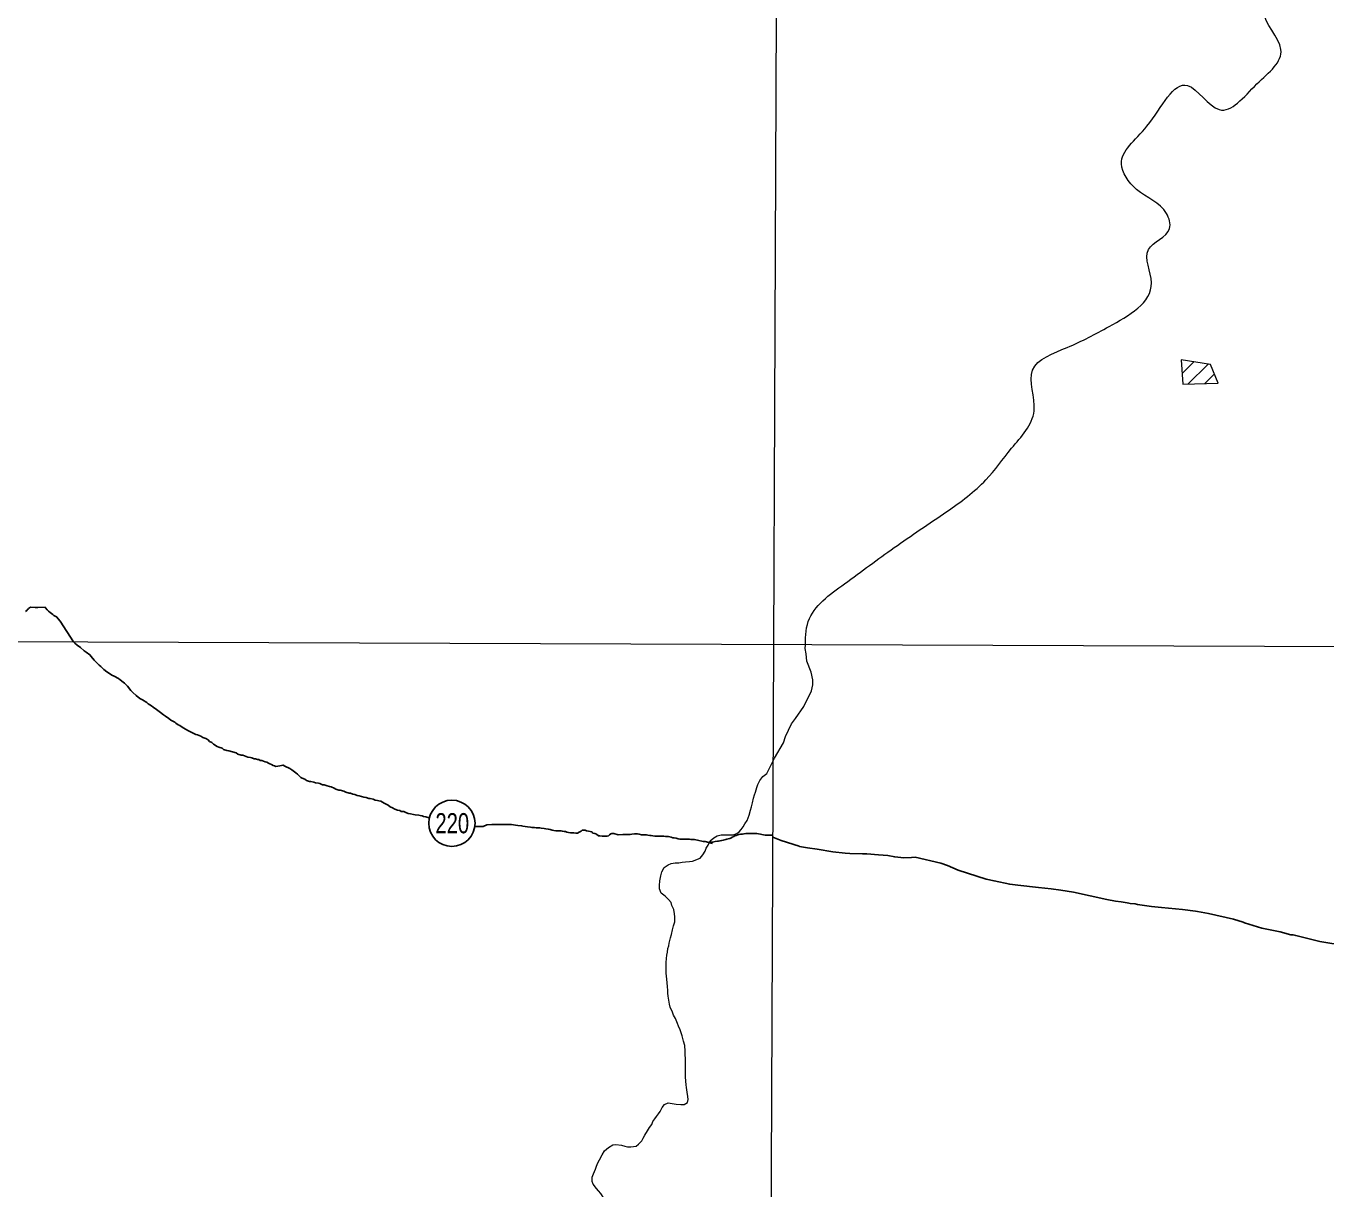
# Model space of a CAD drawing. Extents: x 553962 to 842807, y 8883888 to 9032388.
# Drawn here: x 593998 to 598511, y 8908040 to 8912077 of the extents above; entities that cross this region are included whole.
import ezdxf
from ezdxf.enums import TextEntityAlignment as Align

# ---------------------------------------------------------------- set-up
doc = ezdxf.new("R2010")
doc.units = 0
doc.header["$LTSCALE"] = 160
doc.layers.add('6', color=7, linetype='Continuous', lineweight=13)

msp = doc.modelspace()

# ---------------------------------------------------------------- linework, layer by layer
at = {"layer": '6'}
for p, q in [((598011.9, 8910870), (598052.8, 8910910.9)), ((598032.2, 8910833.7), (598101.8, 8910903.3)), ((598090.8, 8910835.7), (598123.8, 8910868.8)), ((576954.3, 8910001), (623612.7, 8909833))]:
    msp.add_line(p, q, dxfattribs=at)
at = {"layer": '6', "lineweight": 25}
msp.add_line((596590.3, 8909268.1), (596591.5, 8909261.3), dxfattribs=at)
at = {"layer": '6'}
for points in [[(596655.5, 8924715.8), (596593.3, 8909930.3), (596541.3, 8898204.5)], [(596627.8, 8909589.1), (596635.4, 8909611), (596655.3, 8909654), (596669.8, 8909672.5), (596698.4, 8909714.8), (596724.9, 8909769.1), (596729.8, 8909790.3), (596729.5, 8909807.5), (596724.5, 8909833.3), (596708.7, 8909872.6), (596708.4, 8909884.4), (596706.9, 8909897.8), (596703.8, 8909915.9)], [(596275.7, 8909174.6), (596288.2, 8909175.5), (596301.7, 8909176.9), (596311.7, 8909178.4), (596338.8, 8909188.3), (596347.8, 8909199.7), (596355.9, 8909212.7), (596359.4, 8909222.7), (596366.5, 8909233.7), (596373.6, 8909248.1), (596385.6, 8909259.1), (596397.7, 8909265.5), (596411.7, 8909268.9), (596453.7, 8909268.7), (596465.8, 8909273.5), (596474, 8909279.4), (596480.5, 8909287.6), (596487.5, 8909297.6), (596493.4, 8909307), (596502, 8909319.5), (596508.7, 8909337), (596514, 8909354.6), (596516.7, 8909367), (596520.3, 8909380.5), (596523.9, 8909397), (596527.4, 8909408), (596531, 8909417.9), (596535.1, 8909433.9), (596539.1, 8909443.9), (596545.7, 8909457.9), (596556.2, 8909471.9), (596569.8, 8909481.8), (596597.3, 8909535.3), (596627.8, 8909589.1)], [(596220.8, 8908789.1), (596221, 8908826.6), (596222.1, 8908840.6), (596223.1, 8908851.1), (596225.2, 8908861.6), (596226.2, 8908874.6), (596230.3, 8908884.1), (596230.8, 8908893.6), (596235.4, 8908912.1), (596239, 8908923.6), (596243, 8908940.1), (596246.6, 8908953.6), (596250.7, 8908967.6), (596250.8, 8908984.6), (596249.8, 8908995.6), (596247.4, 8909010.6), (596240.9, 8909023.6), (596237.5, 8909034.2), (596228.5, 8909045.2), (596217.1, 8909056.8), (596203.1, 8909066.9), (596197.7, 8909081.4), (596197.7, 8909093.9), (596198.3, 8909109.9), (596201.9, 8909127.4), (596205.9, 8909140.9), (596214, 8909155.9), (596227.1, 8909164.8), (596238.6, 8909169.8), (596251.6, 8909171.7), (596265.1, 8909172.6), (596275.7, 8909174.6)], [(595978.5, 8908119.2), (595983.6, 8908131.2), (595989.1, 8908141.2), (595998.7, 8908158.2), (596006.8, 8908172.2), (596020.8, 8908184.6), (596035.4, 8908193.5), (596045.9, 8908194), (596065.9, 8908192.4), (596076.9, 8908188.3), (596086.9, 8908186.8), (596097.9, 8908186.7), (596116.5, 8908188.6), (596125, 8908195.1), (596136.1, 8908207.5), (596141.1, 8908216), (596146.2, 8908226.5), (596156.2, 8908242.4), (596163.3, 8908252.9), (596170.8, 8908264.4), (596174.9, 8908274.4), (596180.9, 8908283.3), (596187, 8908291.3), (596194, 8908300.8), (596199.6, 8908309.3), (596207.2, 8908323.2), (596215.2, 8908333.7), (596227.7, 8908339.2), (596241.2, 8908336.6), (596255.7, 8908334.5), (596271.8, 8908333.4), (596283.3, 8908333.4), (596295.1, 8908339.9), (596297.3, 8908350.8), (596295.4, 8908360.8), (596293, 8908375.8), (596291.5, 8908391.9), (596290.6, 8908401.9), (596288.6, 8908413.9), (596288.2, 8908429.9), (596287.8, 8908446.9), (596288, 8908490.5), (596286.6, 8908508), (596286.1, 8908518), (596285.2, 8908537.5), (596281.3, 8908553.1), (596275.8, 8908571.1), (596272.4, 8908582.1), (596269.5, 8908592.7), (596263.5, 8908604.7), (596260, 8908614.2), (596252.6, 8908632.3), (596246.7, 8908642.8), (596243.2, 8908653.3), (596234.8, 8908671.4), (596232.8, 8908681.4), (596229.9, 8908695.4), (596228, 8908709), (596227, 8908719.5), (596226, 8908729), (596225.1, 8908743), (596223.7, 8908756), (596222.7, 8908768.5), (596221.8, 8908778.6), (596220.8, 8908789.1)], [(596014.3, 8907828.6), (596014.4, 8907881.9), (596016.5, 8907895.9), (596018.1, 8907906.9), (596021.6, 8907919.9), (596026.2, 8907932.8), (596029.8, 8907948.8), (596029.8, 8907966.3), (596024.4, 8907980.4), (596014.5, 8907995), (596004, 8908008), (595994.1, 8908024.1), (595986.1, 8908034.1), (595979.2, 8908041.2), (595966.7, 8908056.8), (595963.3, 8908066.3), (595963.8, 8908080.8), (595967.9, 8908092.8), (595975, 8908108.8), (595978.5, 8908119.2)]]:
    msp.add_lwpolyline(points, dxfattribs=at)
msp.add_lwpolyline([(598009.1, 8910917.7), (598014.1, 8910833.1), (598136.5, 8910837.3), (598110.5, 8910902)], close=True, dxfattribs=at)
at = {"layer": '6', "lineweight": 25}
for points in [[(593996.3, 8910044), (594000.9, 8910048.2), (594004.6, 8910052.2), (594005.8, 8910052.6), (594007.4, 8910054.3), (594010.6, 8910056.6)], [(594010.6, 8910056.6), (594013.9, 8910058.9), (594030.2, 8910058), (594039.3, 8910057.8), (594065.1, 8910059.8)], [(594065.1, 8910059.8), (594065.3, 8910056.9), (594071.5, 8910049.8), (594076.6, 8910045.4), (594082, 8910041.4), (594090.9, 8910033.6), (594094.4, 8910030.9), (594104.6, 8910026.1), (594117, 8910011.3), (594163.5, 8909939)], [(594163.5, 8909939), (594167.3, 8909934.5), (594175.7, 8909928), (594187.2, 8909918.9), (594200.6, 8909908.3), (594207.6, 8909903.2), (594220, 8909894.1), (594224.9, 8909888.6), (594235.3, 8909875), (594240.8, 8909869.4), (594251.7, 8909858.4), (594257.7, 8909853.3), (594268.6, 8909842.7), (594279.1, 8909834.7), (594284, 8909831.1), (594296.5, 8909824), (594304.5, 8909820), (594319.4, 8909811.8), (594324.9, 8909807.3), (594335.3, 8909799.2), (594340.3, 8909795.2), (594350.2, 8909785.6)], [(594350.2, 8909785.6), (594361.6, 8909770.5), (594369.1, 8909762.9), (594381, 8909752.9), (594393.9, 8909742.8), (594402.4, 8909737.7), (594417.8, 8909728.1), (594422.8, 8909724), (594433.7, 8909717), (594439.7, 8909712.9), (594451.2, 8909704.8), (594456.1, 8909700.8), (594465.6, 8909694.2), (594476, 8909686.1), (594482, 8909681.1), (594493.9, 8909672.5), (594500.9, 8909667.4), (594514.3, 8909659.8), (594518.8, 8909656.8), (594526.8, 8909651.2), (594532.2, 8909648.2), (594543.7, 8909641.1), (594553.7, 8909634.6), (594559.6, 8909631.5), (594571.6, 8909625.9), (594576.6, 8909622.9), (594587.5, 8909617.8), (594593, 8909616.8), (594605.5, 8909612.2), (594612.5, 8909607.1), (594622, 8909603.6), (594630.4, 8909598.5), (594635.4, 8909593.4), (594643.8, 8909589.4), (594649.3, 8909584.3), (594661.8, 8909576.2), (594667.2, 8909573.2), (594678.7, 8909569.6), (594684.2, 8909565.6), (594695.7, 8909561.5), (594702.7, 8909561), (594715.6, 8909557.9), (594727.6, 8909553.8), (594733.6, 8909549.7), (594745.1, 8909546.2), (594751.1, 8909546.1), (594763, 8909541.5), (594768.5, 8909538.5), (594777.5, 8909537.9), (594782, 8909536.4), (594790, 8909533.3), (594795.5, 8909532.8), (594801.5, 8909531.3), (594806, 8909530.7), (594811.5, 8909527.7), (594816.5, 8909527.2), (594822.4, 8909525.1), (594828.9, 8909523.1), (594833.9, 8909521), (594840.4, 8909518.5), (594844.9, 8909515.5), (594850.4, 8909513.4), (594855.8, 8909509.4), (594861.3, 8909508.8), (594865.8, 8909506.8), (594879.8, 8909508.2)], [(594879.8, 8909508.2), (594890.9, 8909511.2), (594897.3, 8909507.1), (594913.8, 8909499.5), (594920.8, 8909494.9), (594934.7, 8909484.8), (594940.7, 8909479.3), (594952.1, 8909468.7), (594957.1, 8909465.7), (594966.5, 8909462.1), (594972.5, 8909457.5), (594982.5, 8909454), (594987.5, 8909453.9), (594997, 8909452.4), (595003, 8909449.3), (595013.4, 8909448.8), (595017.9, 8909447.2), (595027.9, 8909443.2), (595033.4, 8909442.6), (595043.4, 8909439.5), (595052.4, 8909436.5), (595057.4, 8909435.4), (595068.3, 8909430.9), (595073.8, 8909427.8), (595084.3, 8909424.2), (595089.3, 8909424.2), (595101.8, 8909420.6), (595108.8, 8909417.1), (595119.7, 8909414), (595124.2, 8909414), (595133.2, 8909410.9), (595140.2, 8909409.4), (595148.2, 8909405.3), (595155.2, 8909404.2), (595163.2, 8909402.7), (595171.2, 8909400.1), (595179.1, 8909398.6), (595188.1, 8909395.5), (595193.1, 8909395), (595203.6, 8909393.4), (595210.1, 8909389.9), (595218.1, 8909388.8), (595223.6, 8909387.3), (595230.1, 8909386.2), (595235.5, 8909382.2), (595241.5, 8909379.2), (595248, 8909375.6), (595255, 8909372.1), (595262.9, 8909367), (595270.9, 8909362.9), (595278.9, 8909358.9), (595287.8, 8909355.3), (595296.3, 8909354.2), (595300.8, 8909350.7), (595310.3, 8909350.2), (595317.3, 8909346.6), (595324.8, 8909343.1), (595332.8, 8909342), (595343.3, 8909340.4), (595349.8, 8909338.9), (595362.2, 8909337.3), (595366.7, 8909335.8), (595373.2, 8909334.7), (595378.2, 8909333.2), (595386.7, 8909331.6), (595397.5, 8909327.7)], [(595557.4, 8909298.7), (595561.5, 8909298.4), (595565.6, 8909298.4), (595574.5, 8909297.8), (595579.1, 8909297.8), (595585.6, 8909297.8), (595597.6, 8909303.7)], [(595597.6, 8909303.7), (595615.6, 8909305.1), (595622.6, 8909305), (595627.6, 8909305), (595639.1, 8909304.9), (595644.1, 8909304.9), (595655.6, 8909304.8), (595662.1, 8909304.8), (595676.6, 8909304.7), (595683.6, 8909304.6), (595697.6, 8909303), (595705.6, 8909302), (595718.6, 8909300.9), (595723.1, 8909299.3), (595731.1, 8909298.3), (595739.6, 8909297.2), (595750.1, 8909295.7), (595754.6, 8909295.1), (595764.1, 8909294.6), (595769.1, 8909294), (595781.6, 8909293), (595787.1, 8909292.4), (595797.6, 8909290.8), (595802.6, 8909290.3), (595811.1, 8909289.3), (595817.6, 8909287.2), (595824.6, 8909285.7), (595831.1, 8909284.1), (595838.1, 8909283.6), (595844.6, 8909283.5), (595850.1, 8909283), (595856.1, 8909282.9), (595860.6, 8909281.9), (595866.1, 8909281.4), (595871, 8909280.3), (595876, 8909278.8), (595881.5, 8909277.8), (595888.5, 8909276.7), (595895, 8909276.2), (595900.5, 8909275.7), (595907.5, 8909275.6), (595913, 8909275.6), (595919.1, 8909278.5), (595925.6, 8909282.5), (595929.6, 8909285.5), (595933.6, 8909285.9), (595939.6, 8909285.9), (595944.6, 8909283.4), (595951.1, 8909281.8), (595957.1, 8909280.8), (595962.1, 8909279.2), (595966.5, 8909274.7), (595972.5, 8909274.2), (595978.5, 8909271.1), (595985.5, 8909266.1), (595990.5, 8909266), (595998.5, 8909265), (596002.5, 8909265), (596008, 8909264.9), (596012, 8909264.9), (596016, 8909264.9), (596020, 8909265.8), (596024, 8909269.8), (596028.6, 8909272.8), (596032.6, 8909273.8), (596038.6, 8909273.7), (596054.5, 8909269.1)], [(596054.5, 8909269.1), (596070.6, 8909270.5), (596075.6, 8909270.5), (596081.1, 8909270.4), (596085.1, 8909270.4), (596096.1, 8909270.8), (596101.6, 8909271.8), (596111.1, 8909272.2), (596117.6, 8909272.2), (596121.6, 8909272.2), (596127.1, 8909271.1), (596135.1, 8909269.6), (596139.6, 8909269.1), (596146.1, 8909269), (596152.1, 8909269), (596156.6, 8909268.4), (596163.6, 8909267.4), (596169.1, 8909266.4), (596174.6, 8909265.3), (596181.6, 8909264.8), (596187.6, 8909264.7), (596193.1, 8909264.2), (596200.1, 8909264.2), (596206.6, 8909264.1), (596212.1, 8909264.1), (596218.6, 8909264), (596224.1, 8909264), (596228.6, 8909263.5), (596233.1, 8909262.4), (596237.6, 8909260.9), (596244, 8909258.8), (596248.5, 8909258.3), (596255.5, 8909257.3), (596262.5, 8909255.2), (596268, 8909254.7), (596273.5, 8909254.7), (596279.5, 8909254.6), (596287.5, 8909254.6), (596292, 8909254), (596301.5, 8909254), (596306.5, 8909253.4), (596312.5, 8909253.4), (596318.5, 8909253.3), (596334, 8909249.2)], [(596334, 8909249.2), (596344.5, 8909247.2), (596349.5, 8909246.1), (596356, 8909245.6), (596381.5, 8909239.4)], [(596381.5, 8909239.4), (596369, 8909243.5), (596375, 8909243.5), (596379, 8909243.4), (596386, 8909244.4), (596390.5, 8909245.9), (596398.5, 8909246.8), (596402.5, 8909247.8), (596407.5, 8909248.3), (596413.6, 8909249.7), (596418.6, 8909250.7), (596423.6, 8909252.2), (596427.6, 8909253.1), (596431.6, 8909254.1), (596435.6, 8909255.1), (596441.6, 8909257), (596445.6, 8909258), (596449.7, 8909261), (596455.2, 8909263), (596459.7, 8909266.4), (596463.7, 8909267.4), (596469.2, 8909269.4), (596473.2, 8909270.4), (596479.2, 8909271.3), (596485.8, 8909271.8), (596490.8, 8909272.7), (596497.8, 8909274.2), (596501.8, 8909274.2), (596507.3, 8909274.1), (596511.3, 8909274.1), (596515.3, 8909274.1), (596519.3, 8909274.1), (596524.3, 8909274), (596528.3, 8909274), (596534.8, 8909273.9), (596541.3, 8909272.4), (596547.8, 8909271.4), (596553.3, 8909270.3), (596558.3, 8909269.8), (596564.3, 8909268.2), (596568.3, 8909268.2), (596574.3, 8909268.2), (596580.3, 8909268.1), (596585.8, 8909268.1), (596590.3, 8909268.1)], [(596591.5, 8909261.3), (596619.6, 8909249.8), (596682.6, 8909229.6), (596683.9, 8909229.3)], [(596683.9, 8909229.3), (596711.5, 8909223.7), (596744.5, 8909219.2), (596799.3, 8909210.1), (596842.1, 8909206.1)], [(596842.1, 8909206.1), (596858.3, 8909204.6), (596902.4, 8909203.4)], [(596902.4, 8909203.4), (596917, 8909203.1), (596957.6, 8909199.9)], [(596957.6, 8909199.9), (596990.5, 8909197.3), (597014.2, 8909192.9), (597045.7, 8909189.7), (597072.2, 8909191.1)], [(597072.2, 8909191.1), (597084.7, 8909191.8), (597174.5, 8909170.9), (597197.8, 8909163.1), (597234.6, 8909146.1), (597332.2, 8909115.9), (597359.4, 8909109.1), (597359.4, 8909109.1)], [(597359.4, 8909109.1), (597413.5, 8909097.8), (597441.7, 8909094.5)], [(597441.7, 8909094.5), (597513, 8909085.9), (597557.5, 8909082.1), (597590.5, 8909077.7), (597634.7, 8909070.3), (597750.9, 8909045), (597780.8, 8909039.3), (597800, 8909036.6)], [(597800, 8909036.6), (597820.6, 8909033.7), (597826.4, 8909032.4)], [(597826.4, 8909032.4), (597831.3, 8909031.2), (597848.5, 8909029.3), (597857.5, 8909027.9)], [(597857.5, 8909027.9), (597905.8, 8909020.3), (597940, 8909016.9)], [(597940, 8909016.9), (598013.1, 8909009.7), (598058.4, 8909004.1), (598065, 8909003)], [(598065, 8909003), (598103.6, 8908996.2), (598190.4, 8908976.9), (598223.4, 8908965.7), (598229, 8908963.9)], [(598229, 8908963.9), (598288.9, 8908945.4), (598352.3, 8908932.1), (598389.3, 8908922.7), (598397.9, 8908921.9), (598406.4, 8908919.8), (598424.8, 8908915.4)], [(598424.8, 8908915.4), (598490.2, 8908899.6), (598588.7, 8908882.5), (598615.2, 8908875.7), (598623.3, 8908875.6)]]:
    msp.add_lwpolyline(points, dxfattribs=at)
msp.add_circle((595476.7, 8909309.2), 80.3, dxfattribs=at)
at = {"layer": '6'}
msp.add_spline([(596703.8, 8909915.9), (596714.2, 8910009.9), (596839.6, 8910140.6), (597012.1, 8910266), (597195, 8910391.4), (597330.8, 8910501.1), (597419.6, 8910610.8), (597498, 8910741.4), (597492.8, 8910882.5), (597613, 8910960.9), (597759.2, 8911034), (597905.6, 8911185.6), (597895.1, 8911300.5), (597968.2, 8911373.7), (597957.8, 8911425.9), (597853.3, 8911509.5), (597801.1, 8911598.3), (597889.9, 8911729), (598031, 8911870), (598140.7, 8911786.4), (598271.3, 8911875.3), (598354.9, 8911995.4), (598297.4, 8912120.8), (598459.4, 8912178.3), (598694.5, 8912204.4), (598882.6, 8912209.7), (599112.5, 8912314.2), (599201.4, 8912340.3), (599285, 8912455.2), (599384.2, 8912502.3), (599426, 8912612.4), (599520.1, 8912769.3), (599645.5, 8912873.8), (599650.7, 8912967.9), (599603.7, 8913082.9), (599520.1, 8913229.3), (599285, 8913417.5)], degree=3, dxfattribs=at)

# ---------------------------------------------------------------- texts
at = {"layer": '6', "width": 0.75}
msp.add_text('220', height=70, dxfattribs=at).set_placement((595478, 8909274.6), align=Align.CENTER)

doc.saveas('drawing.dxf')
